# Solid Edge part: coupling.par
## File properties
Author: edge
Template: Normal.par
Last saved by: edge
Revision: 12
Application: Solid Edge
文書内容のタイプ: 0
Accuracy: 0.990
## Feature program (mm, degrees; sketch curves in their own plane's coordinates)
sketch for "unnamed Protrusion 1" plane through (0, 0, 0) normal (0, 0, 1) x-axis (1, 0, 0)
  circle centre (0, 0) radius 60
extrude "unnamed Protrusion 1" add finite 20 along +normal
sketch for "ExtrudedProtrusion_2" plane through (0, 0, 0) normal (0, 0, 1) x-axis (1, 0, 0)
  circle centre (0, 0) radius 35
extrude "ExtrudedProtrusion_2" add finite 60 along +normal
sketch for "unnamed Cutout 1" plane through (0, 0, 0) normal (0, 0, 1) x-axis (1, 0, 0)
  circle centre (0, 0) radius 27
extrude "unnamed Cutout 1" cut to key point along +normal
sketch for "Hole_2" plane through (0, 0, 20) normal (0, 0, 1) x-axis (1, 0, 0)
  hole centre (0, 45) bore radius 5
hole "Hole_2" diameter 10 through  CounterBoreDepth = 4 mm
pattern "PatternOccurrence_1" of "Hole_2" along a curve  XDirCount = 4
pattern "unnamed Pattern 1"
sketch for "Hole_3" plane through (0, 0, 20) normal (0, 0, 1) x-axis (1, 0, 0)
  hole centre (30, -30) bore radius 3
hole "Hole_3" diameter 6 through
sketch for "unnamed Cutout 2" plane through (0, 0, 0) normal (0, 0, -1) x-axis (1, 0, 0)
  line (-5, 0) -> (5, 0)
  line (5, 0) -> (5, -31.5)
  line (5, -31.5) -> (-5, -31.5)
  line (-5, -31.5) -> (-5, 0)
extrude "unnamed Cutout 2" cut through along -normal
fillet "Round_1" radius 3
chamfer "Chamfer_1" setback 1
chamfer "Chamfer_2" setback 1
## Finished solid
Body 1: solid body, 25 faces, 37 edges, 8 vertices.
  Faces by surface: cylinder 12, plane 10, cone 2, torus 1
  Edges by curve: circle 27, line 10
Bounding box of the edges (mm; curved faces can reach further): 120.000 x 120.000 x 60.000, from (-60, -60, 0) to (60, 60, 60).
Cylindrical faces by radius (mm): R3 x1, R5 x4, R6.35 x4, R27 x1, R35 x1, R60 x1
Conical faces (half-angle, radius in mm at the cone's reference point): 45 deg R35 x1, 45 deg R60 x1
Toroidal faces (ring radius, tube radius in mm): R38 r3 x1
Planar faces by outward normal: +x 1, +z 6, -x 1, -y 1, -z 1
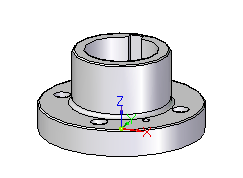
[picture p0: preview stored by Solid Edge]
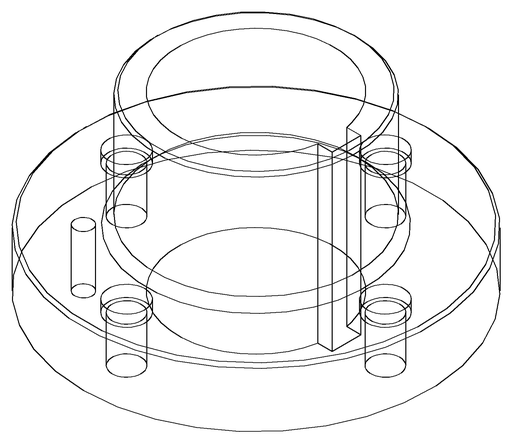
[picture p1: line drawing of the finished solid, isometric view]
